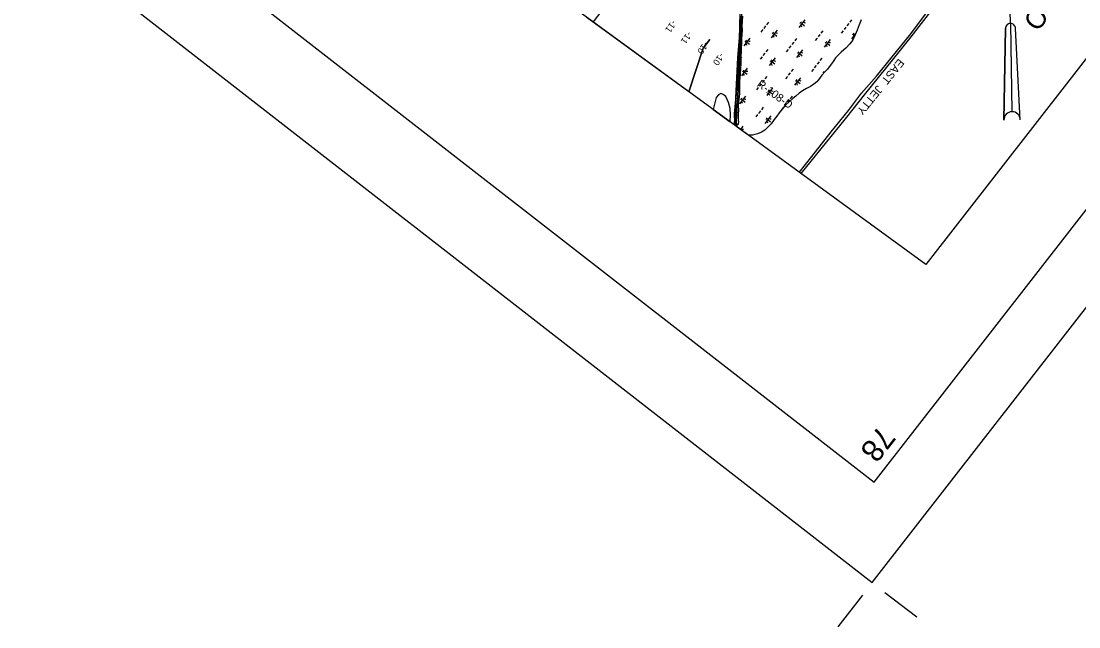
# Model space of a CAD drawing. Extents: x 3888273 to 3909528, y 158682 to 181032.
# Drawn here: x 3893626 to 3899111, y 158682 to 161825 of the extents above; entities that cross this region are included whole.
import ezdxf

# ---------------------------------------------------------------- set-up
doc = ezdxf.new("R2010")
doc.units = 0
for name, color, linetype in [('G-ANNO-NPLT', 7, 'Continuous'), ('V-ANNO-DIMS', 7, 'Continuous'), ('V-ANNO-SYMB', 7, 'Continuous'), ('V-ANNO-TEXT', 7, 'Continuous'), ('V-GRID-FRAM', 7, 'Continuous'), ('V-GRID-MAJR', 7, 'Continuous'), ('V-RIVR-EDGE', 7, 'Continuous'), ('V-RIVR-IDEN', 7, 'Continuous'), ('V-RIVR-JETY', 7, 'Continuous'), ('V-RIVR-RANG', 7, 'Continuous'), ('V-RIVR-RANG-IDEN', 7, 'Continuous'), ('V-RRAP-FSHR', 7, 'Continuous'), ('V-TOPO-DPTH', 7, 'Continuous'), ('V-TOPO-MINR', 7, 'Continuous'), ('V-WETL-SWMP', 7, 'Continuous')]:
    doc.layers.add(name, color=color, linetype=linetype)

msp = doc.modelspace()

# ---------------------------------------------------------------- linework, layer by layer
at = {"layer": 'G-ANNO-NPLT'}
msp.add_lwpolyline([(3899761, 180802.2), (3888502.9, 166332.7), (3898039.6, 158912.6), (3909297.7, 173382)], close=True, dxfattribs=at)
at = {"layer": 'V-ANNO-DIMS'}
for p, q in [((3897988.4, 158846.8), (3897860.5, 158682.4)), ((3898105.3, 158861.4), (3898269.8, 158733.5))]:
    msp.add_line(p, q, dxfattribs=at)
at = {"layer": 'V-ANNO-SYMB'}
for p, q in [((3898756, 161812.2), (3898753.2, 161974.7)), ((3898756, 161812.2), (3898763.9, 161354.7)), ((3898756, 161812.2), (3898763.9, 161354.7)), ((3898722.1, 161311.5), (3898730.4, 161785.7)), ((3898730.4, 161785.7), (3898722.1, 161311.5)), ((3898807.1, 161313), (3898782.4, 161786.6))]:
    msp.add_line(p, q, dxfattribs=at)
msp.add_lwpolyline([(3899163.3, 179525), (3889005.4, 166469.6), (3898048.8, 159433.3), (3908206.7, 172488.7), (3899163.3, 179525)], dxfattribs=at)
for centre, radius, start, end in [((3898756.4, 161786.2), 26, 90.9861, 180.9894), ((3898756.4, 161786.2), 26, 90.9927, 180.9894), ((3898756.4, 161786.2), 26, 0.9894, 90.9927), ((3898764.6, 161312.2), 42.5, 90.9894, 180.9894), ((3898764.6, 161312.2), 42.5, 90.9894, 180.9894), ((3898764.6, 161312.2), 42.5, 0.9894, 90.9894), ((3898764.6, 161312.2), 42.5, 0.9894, 90.9894)]:
    msp.add_arc(centre, radius, start, end, dxfattribs=at)
at = {"layer": 'V-GRID-FRAM'}
msp.add_lwpolyline([(3907415, 172254.2), (3898317.3, 160561.5), (3891517.3, 165521.6), (3900698.9, 177323.8), (3907415, 172254.2)], dxfattribs=at)
at = {"layer": 'V-GRID-MAJR'}
msp.add_spline([(3899339.3, 161091.9), (3899310.2, 162813.4), (3899208, 168873.7), (3899105.7, 174933.9), (3899088.2, 175974.6)], degree=3, dxfattribs=at)
at = {"layer": 'V-RIVR-EDGE'}
msp.add_lwpolyline([(3897376.7, 162376.5), (3897374, 162271.2), (3897360, 162118), (3897353.7, 162085.2), (3897355.3, 161900.7), (3897352.1, 161839.8), (3897349, 161739.7), (3897341.2, 161636.6), (3897323.4, 161286.5)], dxfattribs=at)
at = {"layer": 'V-RIVR-JETY'}
for points in [[(3897661, 161040.1), (3897726.4, 161123.2), (3897826.4, 161250.5), (3897916, 161360.2), (3897984.6, 161451.2), (3898062, 161538.6), (3898143.1, 161638.8), (3898239.5, 161759.3), (3898325.5, 161873.8), (3898339.2, 161890.2), (3898346.5, 161907), (3898351.4, 161931), (3898352.5, 162060.5), (3898351.3, 162198.3), (3898353.8, 162313.2)], [(3898361.6, 162324.9), (3898361.9, 162248.8), (3898358.3, 162011.1), (3898360.2, 161925), (3898361.4, 161919.7), (3898373.5, 161930.1), (3898455.8, 162032.3), (3898463, 162025.4), (3898371, 161912.1), (3898239.4, 161742.8), (3898142.6, 161621.5), (3898004.2, 161451.5), (3897898.5, 161318.2), (3897720.2, 161098.4), (3897668.8, 161034.5)], [(3897345.6, 161306.4), (3897343.9, 161288.7), (3897342.3, 161287.9), (3897339.5, 161288.7), (3897335.5, 161292.8), (3897331.1, 161308.4), (3897331.2, 161326.9), (3897335.5, 161378.3), (3897342.2, 161432.1), (3897343.7, 161480.2), (3897343.1, 161517.6), (3897344.9, 161548.9), (3897347.4, 161579.8), (3897350.9, 161628.8), (3897353.2, 161681.4), (3897355.6, 161753.6), (3897356.7, 161809.5), (3897358.1, 161850.4)], [(3897345.6, 161306.4), (3897346.2, 161311.7), (3897346.7, 161325.6), (3897346.8, 161344), (3897346.9, 161362.1), (3897345.9, 161384.4), (3897347.5, 161404.1), (3897349.9, 161419.1), (3897351.5, 161431.7), (3897352.7, 161449.1), (3897353.3, 161475.6), (3897352.6, 161492.9), (3897353.1, 161512.6), (3897354.3, 161530.6), (3897356.4, 161550.3), (3897358.4, 161578.3), (3897359.3, 161603), (3897359.4, 161618.4), (3897360.3, 161645.3), (3897361.2, 161664.9), (3897361.7, 161684.9), (3897363, 161710.3), (3897363.9, 161733.8), (3897364.7, 161751.8), (3897366.4, 161781.1), (3897365.7, 161800.8), (3897366.2, 161821.9), (3897368, 161850)], [(3897329.1, 161282.2), (3897329.2, 161284.6), (3897337.5, 161284.3), (3897337.2, 161276.3)]]:
    msp.add_lwpolyline(points, dxfattribs=at)
at = {"layer": 'V-RRAP-FSHR'}
msp.add_lwpolyline([(3897334.5, 161278.4), (3897347.1, 161496.1), (3897391.7, 162468.6), (3897415, 162511), (3897527.9, 162698.5), (3897668.8, 162942.7), (3897726.7, 163035.8), (3897814.8, 163180.2), (3897887.5, 163323.2), (3898044.9, 163635.1), (3898398.2, 164233.6), (3898621.6, 164567.9), (3898731.9, 164766.1)], dxfattribs=at)
at = {"layer": 'V-TOPO-DPTH'}
for p, q in [((3897087.9, 161458.2), (3896561.9, 161841.9)), ((3897214, 161366.2), (3897302.8, 161301.4))]:
    msp.add_line(p, q, dxfattribs=at)
for points in [[(3897196.8, 161729.6), (3897162.5, 161685), (3897087.9, 161458.2)], [(3897302.8, 161301.4), (3897303.2, 161304), (3897304.9, 161337.8), (3897302.5, 161370.8), (3897293.7, 161402.8), (3897280.8, 161434.1), (3897266.9, 161444.7), (3897253.7, 161448.4), (3897241.7, 161441.8), (3897230.5, 161428.3), (3897214, 161366.2)]]:
    msp.add_lwpolyline(points, dxfattribs=at)
at = {"layer": 'V-TOPO-MINR'}
for points in [[(3896592.5, 161819.6), (3896593.4, 161820.8), (3896705.8, 161970.2), (3896716.9, 161984.7), (3896728.2, 161999.1), (3896739.6, 162013.4), (3896751.2, 162027.5), (3896795.1, 162080.3)], [(3897087.9, 161458.2), (3897162.5, 161685), (3897196.8, 161729.6)], [(3897302.8, 161301.4), (3897303.2, 161304), (3897304.9, 161337.8), (3897302.5, 161370.8), (3897293.7, 161402.8), (3897280.8, 161434.1), (3897266.9, 161444.7), (3897253.7, 161448.4), (3897241.7, 161441.8), (3897230.5, 161428.3), (3897214, 161366.2)]]:
    msp.add_lwpolyline(points, dxfattribs=at)
at = {"layer": 'V-WETL-SWMP'}
for p, q in [((3897353.2, 161813.3), (3897353.8, 161853.5)), ((3897352.5, 161771.2), (3897353.2, 161813.3)), ((3897486.3, 161799.4), (3897476.5, 161786.8)), ((3897501, 161818.4), (3897491.2, 161805.7)), ((3897689.8, 161831.5), (3897659.1, 161792)), ((3897672.1, 161821.2), (3897664.7, 161811.7)), ((3897674.5, 161811.7), (3897688.7, 161800.7)), ((3897902.9, 161793.2), (3897893.1, 161780.6)), ((3897917.7, 161812.1), (3897907.9, 161799.5)), ((3897932.4, 161831.1), (3897922.6, 161818.4)), ((3897972.1, 161805.2), (3897961, 161778.1)), ((3897981.2, 161830.6), (3897972.1, 161805.2)), ((3897351.5, 161725), (3897352.8, 161754.4)), ((3897352.8, 161754.4), (3897352.5, 161771.2)), ((3897366.1, 161780.2), (3897356.3, 161767.6)), ((3897404.4, 161735.5), (3897373.7, 161696.1)), ((3897471.5, 161780.5), (3897461.7, 161767.8)), ((3897545.7, 161778), (3897515, 161738.5)), ((3897527.9, 161767.7), (3897520.6, 161758.3)), ((3897530.3, 161758.3), (3897544.5, 161747.2)), ((3897647, 161735.1), (3897637.2, 161722.5)), ((3897753.3, 161736.1), (3897743.4, 161723.5)), ((3897768, 161755.1), (3897758.2, 161742.4)), ((3897782.7, 161774), (3897772.9, 161761.4)), ((3897888.2, 161774.2), (3897878.4, 161761.6)), ((3897953.2, 161760), (3897931.6, 161732.3)), ((3897944.6, 161761.5), (3897937.2, 161752)), ((3897950.4, 161753.4), (3897940.5, 161731.6)), ((3897947, 161752), (3897949, 161750.5)), ((3897961, 161778.1), (3897950.4, 161753.4)), ((3897350, 161667.9), (3897350.9, 161695.8)), ((3897350.9, 161695.8), (3897351.5, 161725)), ((3897386.7, 161725.3), (3897379.3, 161715.8)), ((3897389.1, 161715.8), (3897403.3, 161704.8)), ((3897617.6, 161697.3), (3897607.7, 161684.6)), ((3897632.3, 161716.2), (3897622.5, 161703.6)), ((3897821.1, 161729.3), (3897790.4, 161689.9)), ((3897803.4, 161719.1), (3897796, 161709.6)), ((3897805.8, 161709.6), (3897820, 161698.5)), ((3897903.8, 161686.8), (3897878.6, 161663.9)), ((3897921.4, 161705.8), (3897903.8, 161686.8)), ((3897932, 161717.9), (3897921.4, 161705.8)), ((3897940.5, 161731.6), (3897932, 161717.9)), ((3897347.2, 161602.3), (3897350, 161667.9)), ((3897361.6, 161639.2), (3897351.8, 161626.6)), ((3897467.9, 161640.2), (3897458.1, 161627.6)), ((3897482.6, 161659.1), (3897472.8, 161646.5)), ((3897497.4, 161678.1), (3897487.5, 161665.5)), ((3897535.7, 161633.4), (3897505, 161593.9)), ((3897602.8, 161678.3), (3897593, 161665.7)), ((3897677, 161675.9), (3897646.3, 161636.4)), ((3897659.2, 161665.6), (3897651.8, 161656.1)), ((3897661.6, 161656.1), (3897675.8, 161645.1)), ((3897778.3, 161633), (3897768.5, 161620.4)), ((3897849.7, 161634.1), (3897839.9, 161619.9)), ((3897864.7, 161650.2), (3897849.7, 161634.1)), ((3897878.6, 161663.9), (3897864.7, 161650.2)), ((3897342.1, 161566.3), (3897345.5, 161587.3)), ((3897345.5, 161587.3), (3897347.2, 161602.3)), ((3897391.6, 161579.9), (3897360.9, 161540.5)), ((3897518, 161623.1), (3897510.6, 161613.7)), ((3897520.4, 161613.7), (3897534.6, 161602.6)), ((3897628.6, 161575.9), (3897618.8, 161563.3)), ((3897734.1, 161576.2), (3897724.3, 161563.6)), ((3897748.8, 161595.1), (3897739, 161582.5)), ((3897763.6, 161614.1), (3897753.8, 161601.4)), ((3897806.8, 161575.9), (3897793.4, 161561)), ((3897816.6, 161588), (3897806.8, 161575.9)), ((3897827.6, 161603.8), (3897816.6, 161588)), ((3897839.9, 161619.9), (3897827.6, 161603.8)), ((3897338.1, 161500.2), (3897339, 161520.5)), ((3897339, 161520.5), (3897340.8, 161539.5)), ((3897340.8, 161539.5), (3897342.1, 161566.3)), ((3897373.8, 161569.7), (3897366.5, 161560.2)), ((3897376.2, 161560.2), (3897390.4, 161549.1)), ((3897478.2, 161518.1), (3897468.4, 161505.5)), ((3897492.9, 161537.1), (3897483.1, 161524.5)), ((3897599.2, 161538.1), (3897589.3, 161525.4)), ((3897613.9, 161557), (3897604.1, 161544.4)), ((3897667, 161531.3), (3897636.3, 161491.8)), ((3897649.2, 161521), (3897641.9, 161511.5)), ((3897766.1, 161526.3), (3897751.8, 161510.2)), ((3897778.3, 161543.7), (3897766.1, 161526.3)), ((3897793.4, 161561), (3897778.3, 161543.7)), ((3897790.5, 161563.4), (3897783.1, 161554)), ((3897335.8, 161450), (3897338, 161474.7)), ((3897343.3, 161480), (3897337.8, 161473.1)), ((3897338, 161474.7), (3897338.1, 161500.2)), ((3897448.7, 161480.3), (3897438.9, 161467.6)), ((3897463.5, 161499.2), (3897453.6, 161486.6)), ((3897522.9, 161477.8), (3897492.2, 161438.3)), ((3897505.1, 161467.5), (3897497.7, 161458.1)), ((3897651.7, 161511.5), (3897665.9, 161500.5)), ((3897677, 161462.4), (3897659.9, 161450.7)), ((3897698.1, 161474.8), (3897677, 161462.4)), ((3897719.3, 161486.1), (3897698.1, 161474.8)), ((3897737.1, 161496.9), (3897719.3, 161486.1)), ((3897751.8, 161510.2), (3897737.1, 161496.9)), ((3897331.1, 161400.6), (3897333.7, 161426.1)), ((3897333.7, 161426.1), (3897335.8, 161450)), ((3897381.6, 161435.3), (3897350.9, 161395.9)), ((3897363.9, 161425.1), (3897356.5, 161415.6)), ((3897366.3, 161415.6), (3897380.5, 161404.6)), ((3897507.5, 161458.1), (3897521.7, 161447)), ((3897609.5, 161416), (3897599.6, 161403.4)), ((3897627.4, 161423), (3897608.2, 161405.2)), ((3897624.2, 161434.9), (3897614.4, 161422.3)), ((3897642.4, 161436.2), (3897627.4, 161423)), ((3897659.9, 161450.7), (3897642.4, 161436.2)), ((3897325.6, 161346), (3897327.3, 161363)), ((3897327.3, 161363), (3897329, 161378.4)), ((3897329, 161378.4), (3897331.1, 161400.6)), ((3897459.8, 161358.9), (3897450, 161346.3)), ((3897474.5, 161377.9), (3897464.7, 161365.2)), ((3897572, 161367.8), (3897556.1, 161348.4)), ((3897580, 161378.1), (3897571, 161366.6)), ((3897589.9, 161388.3), (3897572, 161367.8)), ((3897594.7, 161397.1), (3897584.9, 161384.4)), ((3897608.2, 161405.2), (3897589.9, 161388.3)), ((3897324.7, 161331), (3897325.6, 161346)), ((3897327, 161312.3), (3897324.7, 161331)), ((3897328.6, 161302.2), (3897327, 161312.3)), ((3897331.7, 161290), (3897328.6, 161302.2)), ((3897338.8, 161339), (3897329, 161326.4)), ((3897445.1, 161340), (3897435.2, 161327.4)), ((3897512.9, 161333.2), (3897482.2, 161293.7)), ((3897495.1, 161322.9), (3897487.8, 161313.5)), ((3897497.5, 161313.5), (3897511.8, 161302.4)), ((3897530.4, 161313.7), (3897515.3, 161292.3)), ((3897544.2, 161331.4), (3897530.4, 161313.7)), ((3897556.1, 161348.4), (3897544.2, 161331.4)), ((3897336.5, 161278.7), (3897331.7, 161290)), ((3897339.4, 161274.8), (3897336.5, 161278.7)), ((3897394.5, 161234.5), (3897339.4, 161274.8)), ((3897351, 161269.5), (3897349.4, 161267.4)), ((3897368.8, 161279.7), (3897355.7, 161262.9)), ((3897465.6, 161248.4), (3897444.5, 161240)), ((3897482.3, 161258.4), (3897465.6, 161248.4)), ((3897496.9, 161272.1), (3897482.3, 161258.4)), ((3897515.3, 161292.3), (3897496.9, 161272.1)), ((3897406, 161233.3), (3897394.5, 161234.5)), ((3897418.1, 161233.7), (3897406, 161233.3)), ((3897431.1, 161236), (3897418.1, 161233.7)), ((3897444.5, 161240), (3897431.1, 161236))]:
    msp.add_line(p, q, dxfattribs=at)
for centre, start, end in [((3897657.7, 161789.8), 11.343, 52.8866), ((3897691.6, 161833.4), 231.343, 272.8866), ((3897513.6, 161736.3), 11.343, 52.8866), ((3897547.5, 161779.9), 231.343, 272.8866), ((3897930.2, 161730.1), 35.8777, 52.8866), ((3897964.1, 161773.7), 231.343, 231.4701), ((3897372.3, 161693.9), 11.343, 52.8866), ((3897406.2, 161737.5), 231.343, 272.8866), ((3897789, 161687.6), 11.343, 52.8866), ((3897822.9, 161731.2), 231.343, 272.8866), ((3897644.8, 161634.2), 11.343, 52.8866), ((3897678.8, 161677.8), 231.343, 272.8866), ((3897503.6, 161591.7), 11.343, 52.8866), ((3897537.5, 161635.3), 231.343, 272.8866), ((3897359.4, 161538.3), 11.343, 52.8866), ((3897393.4, 161581.9), 231.343, 272.8866), ((3897668.8, 161533.2), 231.343, 272.8866), ((3897524.7, 161479.7), 231.343, 272.8866), ((3897634.9, 161489.6), 11.343, 52.8866), ((3897349.5, 161393.7), 11.343, 52.8866), ((3897383.4, 161437.3), 231.343, 272.8866), ((3897490.7, 161436.1), 11.343, 52.8866), ((3897480.8, 161291.5), 11.343, 52.8866), ((3897514.7, 161335.1), 231.343, 272.8866), ((3897370.5, 161281.6), 231.343, 272.8866)]:
    msp.add_arc(centre, 17.6, start, end, dxfattribs=at)

# ---------------------------------------------------------------- texts
at = {"layer": 'V-ANNO-TEXT'}
msp.add_text('78', height=115, rotation=232.1148, dxfattribs=at).set_placement((3898076.6, 159732.3))
at = {"layer": 'V-RIVR-IDEN'}
msp.add_text('MEXICO', height=100, rotation=232.1185, dxfattribs=at).set_placement((3899141.5, 162243.5))
at = {"layer": 'V-RIVR-JETY'}
msp.add_text('EAST  JETTY', height=42, rotation=231.1746, dxfattribs=at).set_placement((3898176.3, 161632.9))
at = {"layer": 'V-RIVR-RANG'}
for s, p in [('-11', (3897001.8, 161832.5)), ('-11', (3897082.8, 161773.9)), ('-10', (3897168.2, 161721.3)), ('-10', (3897249.2, 161662.7))]:
    msp.add_text(s, height=33.5, rotation=233.9783, dxfattribs=at).set_placement(p)
at = {"layer": 'V-RIVR-RANG-IDEN'}
msp.add_text('R-108-D', height=41.5, rotation=324.1197, dxfattribs=at).set_placement((3897438.5, 161490.1))

doc.saveas('drawing.dxf')
